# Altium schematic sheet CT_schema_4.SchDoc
size 218 x 258 mm
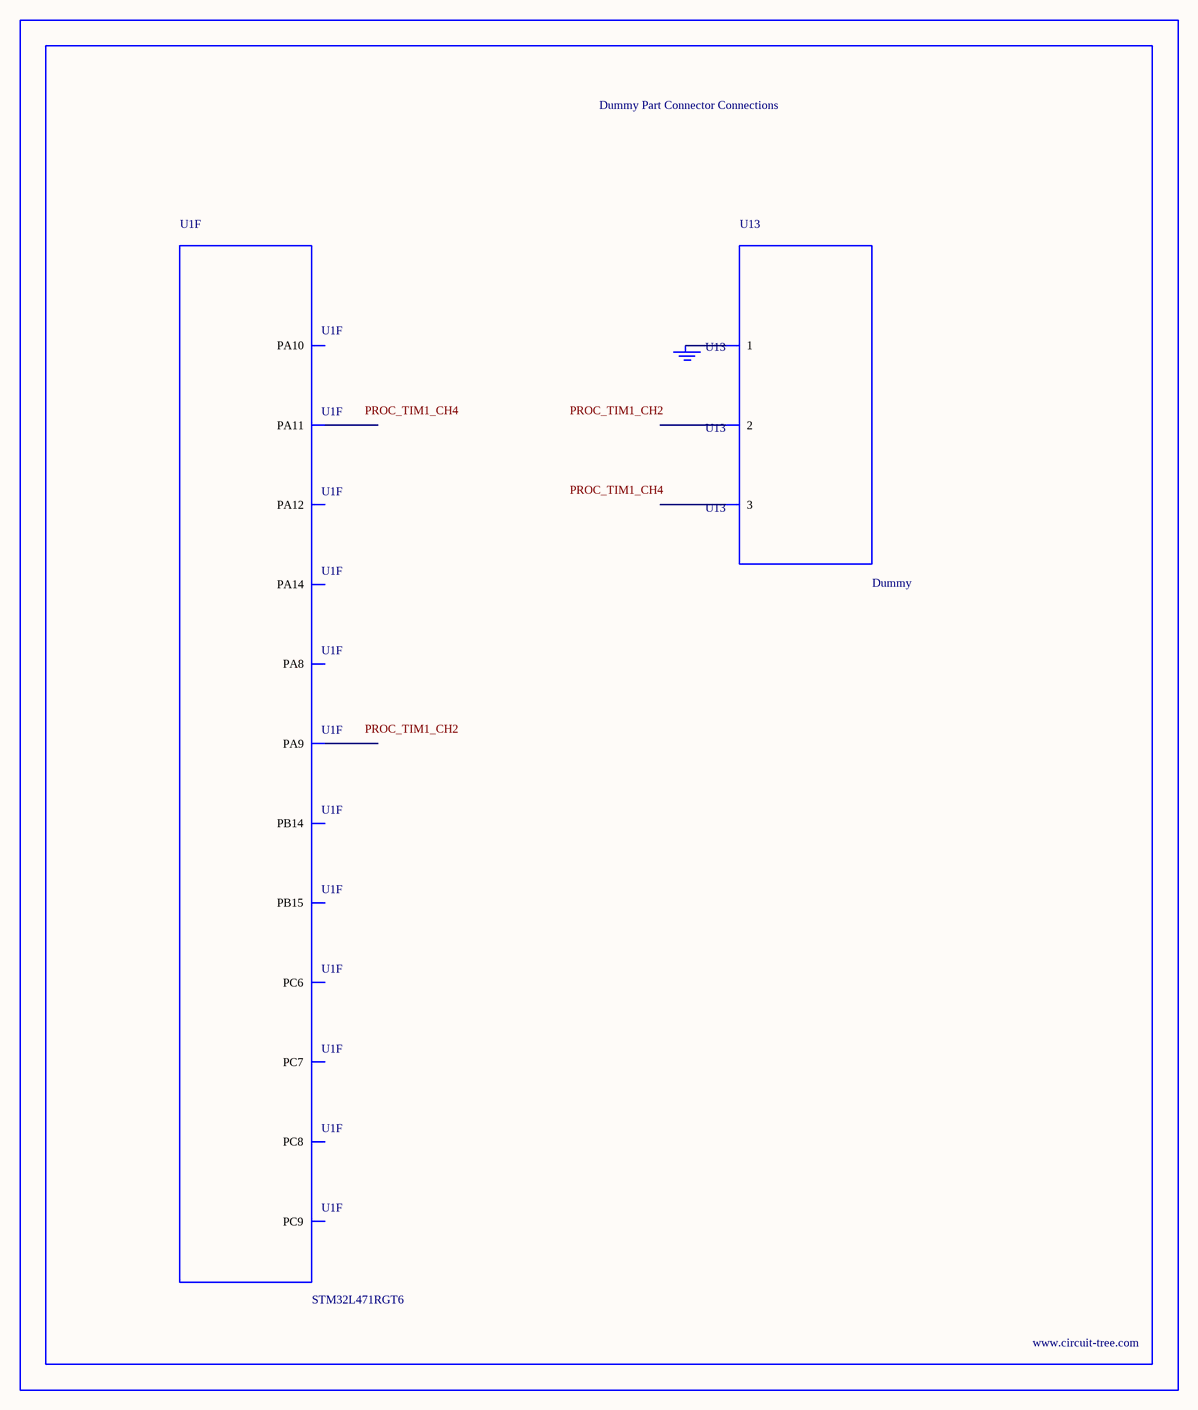
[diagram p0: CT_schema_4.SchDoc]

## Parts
BORDER3  (no value)
GND_INSTANCE_3_0  (no value)
U1  STM32L471RGT6  [LQFP64]  (part F of 6)
U13  Dummy  [DUMMY_PACKAGE_127]

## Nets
NetGND_INSTANCE_3_0_0: GND_INSTANCE_3_0.0(GND) U13.1

Not connected (* = marked no-connect by the designer): U1 35(PB14) 36(PB15) 37(PC6) 38(PC7) 39(PC8) 40(PC9) 41(PA8) 42(PA9) 43(PA10) 44(PA11) 45(PA12) 49(PA14); U13 2 3

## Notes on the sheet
- Labels drawn without touching a wire or pin: PROC_TIM1_CH2, PROC_TIM1_CH4

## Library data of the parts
BORDER3 = BORDER_PAGE3
GND_INSTANCE_3_0 = GND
